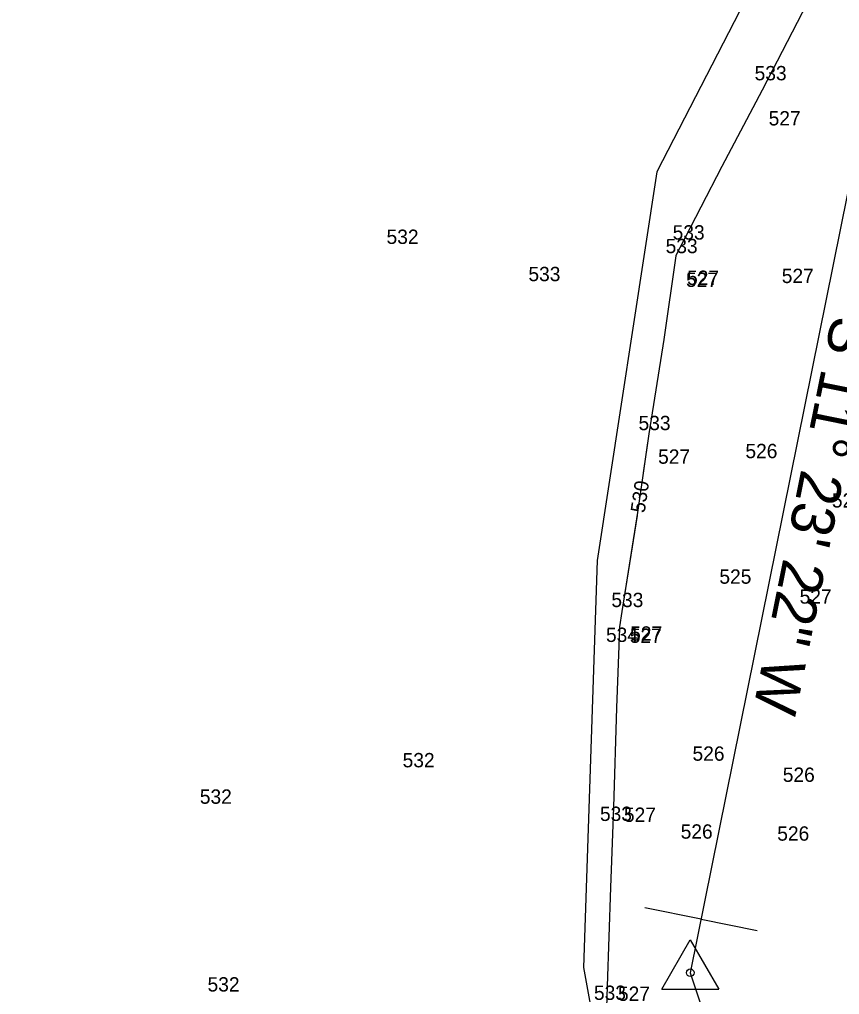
# Model space of a CAD drawing. Extents: x 1787461 to 1970323, y 938412 to 1118748.
# Drawn here: x 1967710 to 1967824.4, y 1117941.2 to 1118077.3 of the extents above; entities that cross this region are included whole.
import ezdxf

# ---------------------------------------------------------------- set-up
doc = ezdxf.new("R2010")
doc.units = 0
for name, color, linetype in [('Default', 7, 'Continuous'), ('HHA ADDITIONAL XSs', 7, 'Continuous'), ('RD_EX_DV_Prop', 7, 'Continuous'), ('RD_EX_H2O', 7, 'Continuous'), ('RD_HC_CL', 7, 'Continuous'), ('RD_HC_Data', 7, 'Continuous'), ('RD_HC_Data_Tic', 7, 'Continuous'), ('RD_PD_Final_TrvlWay', 7, 'Continuous'), ('RD_SMD_Locator', 7, 'Continuous')]:
    doc.layers.add(name, color=color, linetype=linetype)

msp = doc.modelspace()

# ---------------------------------------------------------------- linework, layer by layer
at = {"layer": 'Default'}
for points in [[(1967902.47, 1118174.31), (1967895.58, 1118169.76), (1967887.93, 1118164.05), (1967875.39, 1118155.74), (1967867.37, 1118149.75), (1967855.82, 1118142.06), (1967848.87, 1118136.87), (1967843.85, 1118127.2), (1967837.66, 1118114.55), (1967832.51, 1118104.67), (1967826.45, 1118092.23), (1967826.08, 1118091.53), (1967825.08, 1118089.48), (1967819.89, 1118079.58), (1967813.61, 1118067.44), (1967808.01, 1118056.77), (1967802.13, 1118045.42), (1967801.64, 1118044.48), (1967801.57, 1118044.34), (1967799.9, 1118032.65), (1967797.82, 1118019.49), (1967797.03, 1118014.01)], [(1967902.47, 1118174.31), (1967895.58, 1118169.76), (1967887.93, 1118164.05), (1967875.39, 1118155.74), (1967867.37, 1118149.75), (1967855.82, 1118142.06), (1967848.87, 1118136.87), (1967843.85, 1118127.2), (1967837.66, 1118114.55), (1967832.51, 1118104.67), (1967826.45, 1118092.23), (1967826.08, 1118091.53), (1967825.08, 1118089.48), (1967819.89, 1118079.58), (1967813.61, 1118067.44), (1967808.01, 1118056.77), (1967802.13, 1118045.42), (1967801.64, 1118044.48), (1967801.57, 1118044.34), (1967799.9, 1118032.65), (1967797.82, 1118019.49), (1967797.03, 1118014.01)], [(1967902.47, 1118174.31), (1967895.58, 1118169.76), (1967887.93, 1118164.05), (1967875.39, 1118155.74), (1967867.37, 1118149.75), (1967855.82, 1118142.06), (1967848.87, 1118136.87), (1967843.85, 1118127.2), (1967837.66, 1118114.55), (1967832.51, 1118104.67), (1967826.45, 1118092.23), (1967826.08, 1118091.53), (1967825.08, 1118089.48), (1967819.89, 1118079.58), (1967813.61, 1118067.44), (1967808.01, 1118056.77), (1967802.13, 1118045.42), (1967801.64, 1118044.48), (1967801.57, 1118044.34), (1967799.9, 1118032.65), (1967797.82, 1118019.49), (1967797.03, 1118014.01)], [(1967902.47, 1118174.31), (1967895.58, 1118169.76), (1967887.93, 1118164.05), (1967875.39, 1118155.74), (1967867.37, 1118149.75), (1967855.82, 1118142.06), (1967848.87, 1118136.87), (1967843.85, 1118127.2), (1967837.66, 1118114.55), (1967832.51, 1118104.67), (1967826.45, 1118092.23), (1967826.08, 1118091.53), (1967825.08, 1118089.48), (1967819.89, 1118079.58), (1967813.61, 1118067.44), (1967808.01, 1118056.77), (1967802.13, 1118045.42), (1967801.64, 1118044.48), (1967801.57, 1118044.34), (1967799.9, 1118032.65), (1967797.82, 1118019.49), (1967797.03, 1118014.01)], [(1967902.47, 1118174.31), (1967895.58, 1118169.76), (1967887.93, 1118164.05), (1967875.39, 1118155.74), (1967867.37, 1118149.75), (1967855.82, 1118142.06), (1967848.87, 1118136.87), (1967843.85, 1118127.2), (1967837.66, 1118114.55), (1967832.51, 1118104.67), (1967826.45, 1118092.23), (1967826.08, 1118091.53), (1967825.08, 1118089.48), (1967819.89, 1118079.58), (1967813.61, 1118067.44), (1967808.01, 1118056.77), (1967802.13, 1118045.42), (1967801.64, 1118044.48), (1967801.57, 1118044.34), (1967799.9, 1118032.65), (1967797.82, 1118019.49), (1967797.03, 1118014.01)], [(1967902.47, 1118174.31), (1967895.58, 1118169.76), (1967887.93, 1118164.05), (1967875.39, 1118155.74), (1967867.37, 1118149.75), (1967855.82, 1118142.06), (1967848.87, 1118136.87), (1967843.85, 1118127.2), (1967837.66, 1118114.55), (1967832.51, 1118104.67), (1967826.45, 1118092.23), (1967826.08, 1118091.53), (1967825.08, 1118089.48), (1967819.89, 1118079.58), (1967813.61, 1118067.44), (1967808.01, 1118056.77), (1967802.13, 1118045.42), (1967801.64, 1118044.48), (1967801.57, 1118044.34), (1967799.9, 1118032.65), (1967797.82, 1118019.49), (1967797.03, 1118014.01)], [(1967819.89, 1118079.58), (1967813.61, 1118067.44), (1967808.01, 1118056.77), (1967802.13, 1118045.42), (1967801.64, 1118044.48), (1967801.57, 1118044.34), (1967799.9, 1118032.65), (1967797.82, 1118019.49), (1967796.23, 1118008.49), (1967794.04, 1117994.66), (1967793.73, 1117992.51), (1967793.7, 1117992.33), (1967793.3, 1117981.2), (1967792.86, 1117967.35), (1967792.45, 1117956.11), (1967792.01, 1117942.36), (1967791.9, 1117939.31)], [(1967796.17, 1118008.07), (1967794.04, 1117994.66), (1967793.73, 1117992.51), (1967793.7, 1117992.33), (1967793.3, 1117981.2), (1967792.86, 1117967.35), (1967792.45, 1117956.11), (1967792.01, 1117942.36), (1967791.9, 1117939.31)], [(1967796.17, 1118008.07), (1967794.04, 1117994.66), (1967793.73, 1117992.51), (1967793.7, 1117992.33), (1967793.3, 1117981.2), (1967792.86, 1117967.35), (1967792.45, 1117956.11), (1967792.01, 1117942.36), (1967791.9, 1117939.31)], [(1967796.17, 1118008.07), (1967794.04, 1117994.66), (1967793.73, 1117992.51), (1967793.7, 1117992.33), (1967793.3, 1117981.2), (1967792.86, 1117967.35), (1967792.45, 1117956.11), (1967792.01, 1117942.36), (1967791.9, 1117939.31)], [(1967796.17, 1118008.07), (1967794.04, 1117994.66), (1967793.73, 1117992.51), (1967793.7, 1117992.33), (1967793.3, 1117981.2), (1967792.86, 1117967.35), (1967792.45, 1117956.11), (1967792.01, 1117942.36), (1967791.9, 1117939.31)], [(1967796.17, 1118008.07), (1967794.04, 1117994.66), (1967793.73, 1117992.51), (1967793.7, 1117992.33), (1967793.3, 1117981.2), (1967792.86, 1117967.35), (1967792.45, 1117956.11), (1967792.01, 1117942.36), (1967791.9, 1117939.31)], [(1967796.17, 1118008.07), (1967794.04, 1117994.66), (1967793.73, 1117992.51), (1967793.7, 1117992.33), (1967793.3, 1117981.2), (1967792.86, 1117967.35), (1967792.45, 1117956.11), (1967792.01, 1117942.36), (1967791.9, 1117939.31)]]:
    msp.add_lwpolyline(points, dxfattribs=at)
at = {"layer": 'HHA ADDITIONAL XSs'}
msp.add_arc((1968231.34, 1116297.54), 1667.02, 87.72663, 111.99584, dxfattribs=at)
at = {"layer": 'RD_EX_DV_Prop'}
for p, q in [((1967832.81, 1118089.32), (1967803.58, 1117944.23)), ((1967803.58, 1117944.23), (1967823.97, 1117883.41))]:
    msp.add_line(p, q, dxfattribs=at)
at = {"layer": 'RD_EX_H2O'}
msp.add_lwpolyline([(1967847.31, 1118356.81), (1967879.15, 1118347.14), (1967885.7, 1118340.94), (1967895.17, 1118292.21), (1967905.1, 1118241.75), (1967913.15, 1118203.17), (1967903.06, 1118190.95), (1967846.3, 1118148.6), (1967822.76, 1118102.41), (1967798.93, 1118056.05), (1967790.6, 1118001.77), (1967788.7, 1117944.97), (1967797.09, 1117898.55), (1967795.44, 1117890.32)], dxfattribs=at)
at = {"layer": 'RD_HC_CL'}
for p, q in [((1967832.81, 1118089.32), (1967803.58, 1117944.23)), ((1967803.58, 1117944.23), (1967848.59, 1117809.96))]:
    msp.add_line(p, q, dxfattribs=at)
at = {"layer": 'RD_HC_Data'}
for p, q in [((1967799.61, 1117941.94), (1967803.58, 1117948.82)), ((1967803.58, 1117948.82), (1967807.55, 1117941.94)), ((1967799.61, 1117941.94), (1967807.55, 1117941.94))]:
    msp.add_line(p, q, dxfattribs=at)
msp.add_circle((1967803.58, 1117944.23), 0.529, dxfattribs=at)
at = {"layer": 'RD_HC_Data_Tic'}
for q in [(1967797.25, 1117953.29), (1967812.93, 1117950.13)]:
    msp.add_line((1967805.09, 1117951.71), q, dxfattribs=at)
at = {"layer": 'RD_PD_Final_TrvlWay'}
msp.add_arc((1968231.34, 1116297.54), 1648.02, 87.72663, 111.99584, dxfattribs=at)
at = {"layer": 'RD_SMD_Locator'}
msp.add_circle((1967803.58, 1117944.23), 0.001, dxfattribs=at)

# ---------------------------------------------------------------- texts
at = {"layer": 'Default'}
for s, p in [('533', (1967812.56, 1118068.82)), ('527', (1967814.52, 1118062.52)), ('532', (1967761.22, 1118045.98)), ('533', (1967801.13, 1118046.59)), ('533', (1967800.15, 1118044.69)), ('533', (1967781.01, 1118040.78)), ('527', (1967816.35, 1118040.52)), ('527', (1967802.99, 1118039.98)), ('527', (1967803.14, 1118040.26)), ('533', (1967796.37, 1118019.98)), ('526', (1967811.28, 1118016.07)), ('527', (1967799.1, 1118015.29)), ('527', (1967823.34, 1118009.18)), ('525', (1967807.65, 1117998.54)), ('527', (1967818.84, 1117995.76)), ('533', (1967792.58, 1117995.28)), ('534', (1967791.83, 1117990.41)), ('527', (1967795.15, 1117990.28)), ('527', (1967795.2, 1117990.59)), ('526', (1967803.9, 1117973.83)), ('532', (1967763.46, 1117972.91)), ('526', (1967816.49, 1117970.88)), ('532', (1967735.17, 1117967.82)), ('533', (1967790.99, 1117965.42)), ('527', (1967794.33, 1117965.29)), ('526', (1967802.25, 1117962.95)), ('526', (1967815.72, 1117962.67)), ('532', (1967736.25, 1117941.61)), ('533', (1967790.15, 1117940.44)), ('527', (1967793.5, 1117940.3))]:
    msp.add_text(s, height=2, dxfattribs=at).set_placement(p)
msp.add_text('530', height=2, rotation=81.7508, dxfattribs=at).set_placement((1967797.22, 1118008.35))
msp.add_text('530', height=2, rotation=81.7508, dxfattribs=at).set_placement((1967797.22, 1118008.35))
msp.add_text('530', height=2, rotation=81.7508, dxfattribs=at).set_placement((1967797.22, 1118008.35))
msp.add_text('530', height=2, rotation=81.7508, dxfattribs=at).set_placement((1967797.22, 1118008.35))
msp.add_text('530', height=2, rotation=81.7508, dxfattribs=at).set_placement((1967797.22, 1118008.35))
msp.add_text('530', height=2, rotation=81.7508, dxfattribs=at).set_placement((1967797.22, 1118008.35))
at = {"layer": 'RD_HC_Data'}
msp.add_text('S 11%%d 23\' 22" W', height=6, rotation=258.6104, dxfattribs=at).set_placement((1967823.44, 1118036.17))

doc.saveas('drawing.dxf')
